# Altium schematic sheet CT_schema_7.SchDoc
size 278 x 170 mm
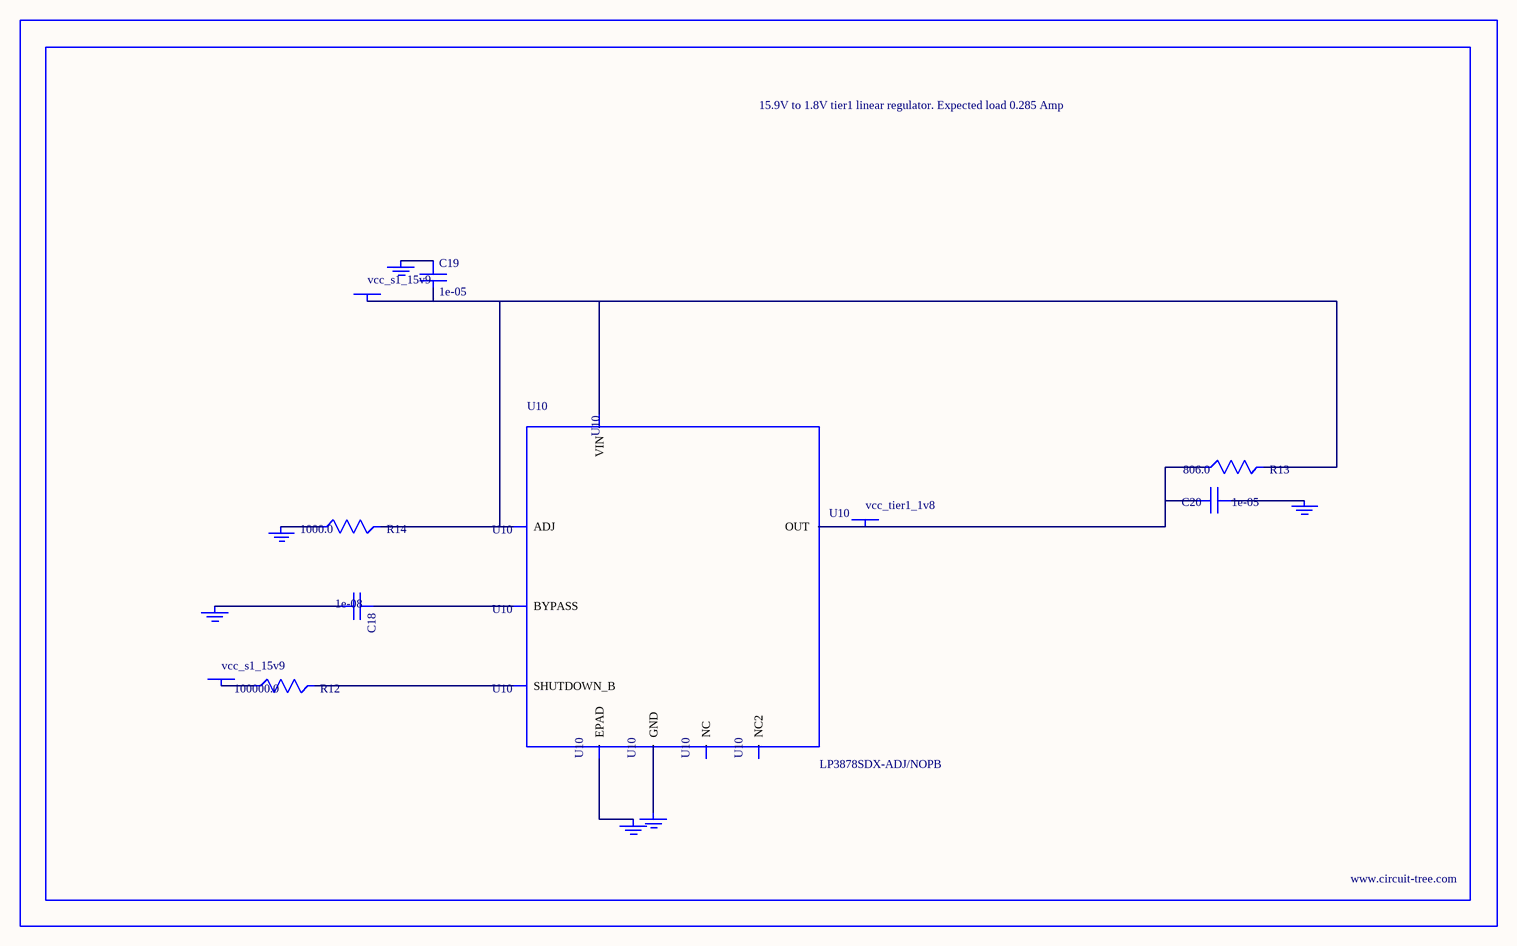
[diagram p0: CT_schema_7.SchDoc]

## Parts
BORDER6  (no value)
C18  1e-08  [C0402]
C19  1e-05  [C1210]
C20  1e-05  [C0805]
GND_INSTANCE_6_0  (no value)
GND_INSTANCE_6_1  (no value)
GND_INSTANCE_6_2  (no value)
GND_INSTANCE_6_3  (no value)
GND_INSTANCE_6_4  (no value)
GND_INSTANCE_6_5  (no value)
POWER_INSTANCE_6_0  vcc_s1_15v9
POWER_INSTANCE_6_1  vcc_s1_15v9
POWER_INSTANCE_6_2  vcc_tier1_1v8
R12  100000.0  [R0603]
R13  806.0  [R0603]
R14  1000.0  [R0603]
U10  LP3878SDX-ADJ/NOPB  [WSON-8]

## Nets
NetC18_1: C18.1 U10.1(BYPASS)
NetC18_2: C18.2 GND_INSTANCE_6_0.0(GND)
NetC19_1: C19.1 GND_INSTANCE_6_1.0(GND)
NetC19_2: C19.2 POWER_INSTANCE_6_0.0(PWR) R13.2 R14.2 U10.4(VIN) U10.6(ADJ)
NetC20_1: C20.1 GND_INSTANCE_6_2.0(GND)
NetC20_2: C20.2 POWER_INSTANCE_6_2.0(PWR) R13.1 U10.5(OUT)
NetGND_INSTANCE_6_3_0: GND_INSTANCE_6_3.0(GND) R14.1
NetGND_INSTANCE_6_4_0: GND_INSTANCE_6_4.0(GND) U10.PAD(EPAD)
NetGND_INSTANCE_6_5_0: GND_INSTANCE_6_5.0(GND) U10.3(GND)
NetPOWER_INSTANCE_6_1_0: POWER_INSTANCE_6_1.0(PWR) R12.1
NetR12_2: R12.2 U10.8(SHUTDOWN_B)

Not connected (* = marked no-connect by the designer): U10 2(NC) 7(NC2)

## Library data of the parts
BORDER6 = BORDER_PAGE6
C18 = C0402C103K3RAC
C19 = C1210C106K5PACTU
C20 = GRM219R60J106ME19D
GND_INSTANCE_6_0-GND_INSTANCE_6_5 = GND
POWER_INSTANCE_6_0-POWER_INSTANCE_6_2 = PWR
R12 = RC0603JR-07100KL
R13 = ERJ-3EKF8060V
R14 = RC0603JR-071KL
